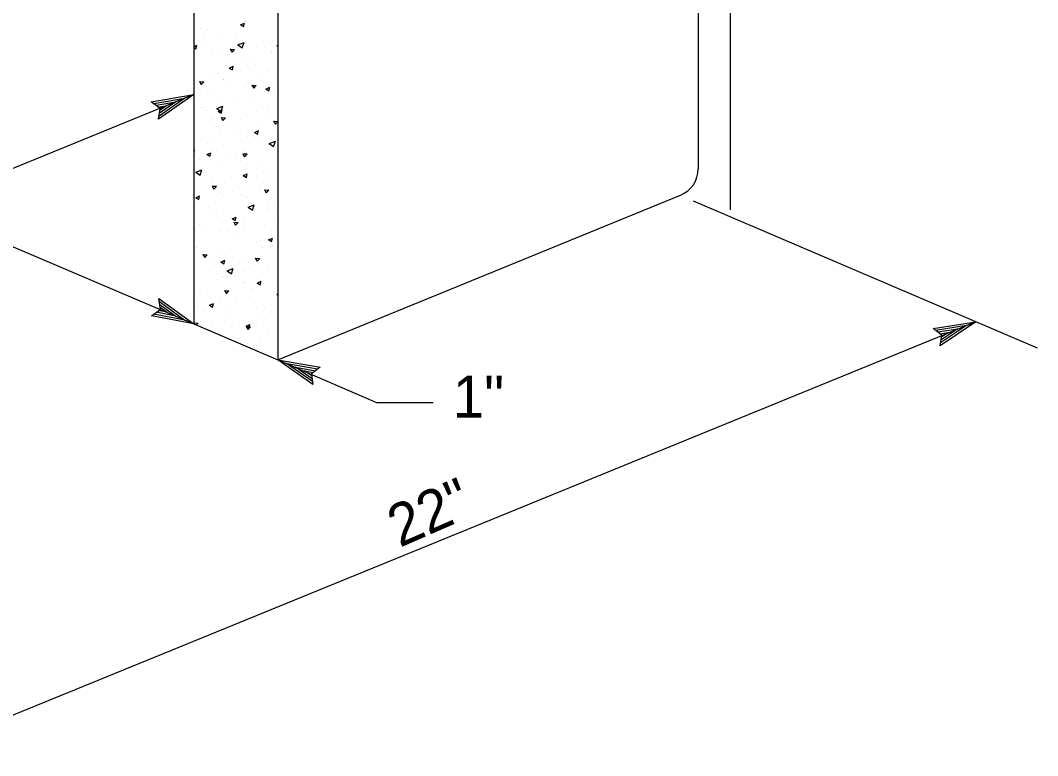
# Model space of a CAD drawing. Extents: x -121875 to -117742, y -103854 to -101122.
# Drawn here: x -120806.9 to -120661.7, y -101531 to -101426.1 of the extents above; entities that cross this region are included whole.
import ezdxf

# ---------------------------------------------------------------- set-up
doc = ezdxf.new("R2010")
doc.units = 0
for name, color, linetype in [('G-MARK', 7, 'Continuous'), ('G-TEXT', 7, 'Continuous'), ('Misc CnstDet(22)', 7, 'Continuous')]:
    doc.layers.add(name, color=color, linetype=linetype)

msp = doc.modelspace()

# ---------------------------------------------------------------- linework, layer by layer
at = {"layer": 'G-MARK'}
for p, q in [((-120862.25, -101435.17), (-120782.14, -101469.41)), ((-120661.71, -101472.87), (-120710.84, -101451.87)), ((-120670.55, -101469.09), (-120822.06, -101531.02))]:
    msp.add_line(p, q, dxfattribs=at)
for points in [[(-120782.14, -101436.65), (-120828.95, -101455.78), (-120827.26, -101459.9), (-120836.23, -101453.95), (-120834.55, -101458.07), (-120895.64, -101483.05)], [(-120770.16, -101474.53), (-120756.08, -101480.63), (-120747.97, -101480.63)]]:
    msp.add_lwpolyline(points, dxfattribs=at)
at = {"layer": 'G-TEXT'}
for p, q in [((-120788.19, -101437.72), (-120782.14, -101436.65)), ((-120787.85, -101437.97), (-120783.41, -101437.18)), ((-120782.14, -101436.65), (-120787.16, -101440.18)), ((-120783.42, -101437.19), (-120787.08, -101439.76)), ((-120782.14, -101436.65), (-120782.14, -101436.65)), ((-120786.94, -101438.65), (-120788.19, -101437.72)), ((-120788.19, -101437.72), (-120788.19, -101437.72)), ((-120787.5, -101438.21), (-120784.69, -101437.71)), ((-120787.2, -101438.46), (-120785.96, -101438.24)), ((-120787.16, -101440.18), (-120786.94, -101438.65)), ((-120784.69, -101437.71), (-120787.05, -101439.37)), ((-120785.96, -101438.24), (-120786.97, -101438.95)), ((-120787.16, -101440.18), (-120787.16, -101440.18)), ((-120786.9, -101467.33), (-120787.1, -101465.78)), ((-120787.1, -101465.78), (-120787.1, -101465.78)), ((-120787.1, -101465.78), (-120782.14, -101469.41)), ((-120787.04, -101466.2), (-120783.4, -101468.86)), ((-120788.17, -101468.23), (-120786.9, -101467.33)), ((-120785.93, -101467.75), (-120787.15, -101467.51)), ((-120786.97, -101466.62), (-120784.67, -101468.3)), ((-120786.95, -101467.01), (-120785.93, -101467.75)), ((-120782.14, -101469.41), (-120788.17, -101468.23)), ((-120788.17, -101468.23), (-120788.17, -101468.23)), ((-120783.41, -101468.86), (-120787.81, -101468)), ((-120784.67, -101468.3), (-120787.51, -101467.75)), ((-120676.63, -101470.06), (-120670.55, -101469.09)), ((-120670.55, -101469.09), (-120675.64, -101472.54)), ((-120670.55, -101469.09), (-120670.55, -101469.09)), ((-120782.14, -101469.41), (-120782.14, -101469.41)), ((-120675.39, -101471.01), (-120676.63, -101470.06)), ((-120676.63, -101470.06), (-120676.63, -101470.06)), ((-120676.29, -101470.31), (-120671.84, -101469.6)), ((-120675.94, -101470.56), (-120673.12, -101470.11)), ((-120675.65, -101470.81), (-120674.41, -101470.62)), ((-120671.85, -101469.61), (-120675.56, -101472.12)), ((-120673.12, -101470.11), (-120675.52, -101471.73)), ((-120674.41, -101470.62), (-120675.43, -101471.31)), ((-120675.64, -101472.54), (-120675.39, -101471.01)), ((-120675.64, -101472.54), (-120675.64, -101472.54)), ((-120765.12, -101478.05), (-120770.16, -101474.53)), ((-120770.16, -101474.53), (-120770.16, -101474.53)), ((-120770.16, -101474.53), (-120764.1, -101475.58)), ((-120765.18, -101477.64), (-120768.88, -101475.06)), ((-120768.87, -101475.06), (-120764.46, -101475.83)), ((-120765.26, -101477.22), (-120767.6, -101475.58)), ((-120767.6, -101475.58), (-120764.75, -101476.08)), ((-120765.29, -101476.83), (-120766.32, -101476.11)), ((-120766.32, -101476.11), (-120765.1, -101476.32)), ((-120764.1, -101475.58), (-120765.35, -101476.51)), ((-120764.1, -101475.58), (-120764.1, -101475.58)), ((-120765.35, -101476.51), (-120765.12, -101478.05)), ((-120765.12, -101478.05), (-120765.12, -101478.05))]:
    msp.add_line(p, q, dxfattribs=at)
at = {"layer": 'Misc CnstDet(22)'}
for p, q in [((-120705.59, -101368.37), (-120705.59, -101453.12)), ((-120710.15, -101383.08), (-120710.15, -101447.27)), ((-120782.14, -101402.21), (-120782.14, -101469.41)), ((-120770.16, -101407.6), (-120770.16, -101474.53)), ((-120775.46, -101426.73), (-120774.89, -101426.47)), ((-120775.46, -101426.73), (-120775.02, -101426.98)), ((-120775.02, -101426.98), (-120774.89, -101426.47)), ((-120774.91, -101426.95), (-120774.91, -101426.95)), ((-120774.85, -101426.21), (-120774.85, -101426.21)), ((-120774.81, -101426.15), (-120774.81, -101426.15)), ((-120782.13, -101428.07), (-120782.13, -101428.07)), ((-120781.22, -101427.25), (-120781.22, -101427.25)), ((-120780.56, -101428.04), (-120780.56, -101428.04)), ((-120780.24, -101427.41), (-120780.24, -101427.41)), ((-120778.18, -101428.2), (-120778.18, -101428.2)), ((-120770.81, -101427.51), (-120770.81, -101427.51)), ((-120782.14, -101429.84), (-120781.69, -101429.64)), ((-120782.14, -101429.97), (-120781.82, -101430.15)), ((-120781.82, -101430.15), (-120781.69, -101429.64)), ((-120781.5, -101429.88), (-120781.5, -101429.88)), ((-120781.01, -101429.83), (-120781.01, -101429.83)), ((-120776.11, -101428.69), (-120776.11, -101428.69)), ((-120775.83, -101429.59), (-120774.96, -101429.25)), ((-120775.83, -101429.59), (-120775.21, -101430.01)), ((-120775.8, -101429.33), (-120775.8, -101429.33)), ((-120775.21, -101430.01), (-120774.96, -101429.26)), ((-120773.12, -101429.8), (-120773.12, -101429.8)), ((-120770.95, -101429), (-120770.95, -101429)), ((-120770.26, -101429.73), (-120770.16, -101429.68)), ((-120770.26, -101429.73), (-120770.16, -101429.79)), ((-120781.56, -101430.26), (-120781.56, -101430.26)), ((-120779.52, -101430.54), (-120779.52, -101430.54)), ((-120778.18, -101430.12), (-120778.18, -101430.12)), ((-120777.37, -101431.16), (-120777.37, -101431.16)), ((-120776.93, -101430.2), (-120776.67, -101430.63)), ((-120776.93, -101430.2), (-120776.3, -101430.25)), ((-120776.67, -101430.64), (-120776.3, -101430.25)), ((-120772.07, -101429.98), (-120772.07, -101429.98)), ((-120771.11, -101430.43), (-120771.11, -101430.43)), ((-120771.04, -101430.63), (-120771.04, -101430.63)), ((-120777.06, -101431.88), (-120777.06, -101431.88)), ((-120777.06, -101432.9), (-120776.49, -101432.64)), ((-120776.63, -101433.15), (-120776.49, -101432.64)), ((-120776.49, -101431.85), (-120776.49, -101431.85)), ((-120774.76, -101431.84), (-120774.76, -101431.84)), ((-120774.49, -101432.48), (-120774.49, -101432.48)), ((-120774.22, -101432.17), (-120774.22, -101432.17)), ((-120773.33, -101432.45), (-120773.33, -101432.45)), ((-120781.47, -101433.26), (-120781.47, -101433.26)), ((-120779.87, -101433.9), (-120779.87, -101433.9)), ((-120778.64, -101433.63), (-120778.64, -101433.63)), ((-120777.06, -101432.9), (-120776.63, -101433.15)), ((-120773.1, -101433.93), (-120773.1, -101433.93)), ((-120771.45, -101433.44), (-120771.45, -101433.44)), ((-120770.27, -101434.22), (-120770.27, -101434.22)), ((-120781.32, -101434.82), (-120781.06, -101435.25)), ((-120781.32, -101434.82), (-120780.69, -101434.87)), ((-120781.06, -101435.25), (-120780.69, -101434.87)), ((-120777.87, -101434.53), (-120777.87, -101434.53)), ((-120777.86, -101434.54), (-120777.86, -101434.54)), ((-120777.52, -101435.31), (-120777.52, -101435.31)), ((-120774.83, -101435.49), (-120774.83, -101435.49)), ((-120774.6, -101434.92), (-120774.6, -101434.92)), ((-120773.84, -101435.35), (-120773.58, -101435.78)), ((-120773.84, -101435.35), (-120773.21, -101435.39)), ((-120773.58, -101435.78), (-120773.21, -101435.39)), ((-120771.86, -101435.9), (-120771.3, -101435.64)), ((-120771.43, -101436.15), (-120771.3, -101435.64)), ((-120781.24, -101436.59), (-120781.24, -101436.59)), ((-120779.9, -101436.1), (-120779.9, -101436.1)), ((-120773.11, -101435.82), (-120773.11, -101435.82)), ((-120771.86, -101435.9), (-120771.43, -101436.15)), ((-120770.41, -101436.19), (-120770.41, -101436.19)), ((-120781.17, -101438.57), (-120781.17, -101438.57)), ((-120780.79, -101438.48), (-120780.79, -101438.48)), ((-120778.84, -101438.67), (-120777.97, -101438.33)), ((-120778.84, -101438.67), (-120778.22, -101439.08)), ((-120778.22, -101439.09), (-120777.97, -101438.33)), ((-120778.2, -101437.55), (-120778.2, -101437.55)), ((-120775.86, -101437.4), (-120775.86, -101437.4)), ((-120773.56, -101437.36), (-120773.56, -101437.36)), ((-120771.68, -101438.66), (-120771.68, -101438.66)), ((-120781.58, -101439.6), (-120781.58, -101439.6)), ((-120780.28, -101438.89), (-120780.28, -101438.89)), ((-120778.66, -101439.07), (-120778.09, -101438.81)), ((-120778.66, -101439.07), (-120778.23, -101439.32)), ((-120778.23, -101439.32), (-120778.09, -101438.81)), ((-120778.23, -101439.97), (-120777.97, -101440.4)), ((-120778.23, -101439.97), (-120777.6, -101440.01)), ((-120777.97, -101440.4), (-120777.6, -101440.01)), ((-120777.13, -101439.87), (-120777.13, -101439.87)), ((-120773.14, -101439.14), (-120773.14, -101439.14)), ((-120771.13, -101439.78), (-120771.13, -101439.78)), ((-120779.67, -101440.24), (-120779.67, -101440.24)), ((-120779.24, -101441.39), (-120779.24, -101441.39)), ((-120776.83, -101440.54), (-120776.83, -101440.54)), ((-120776.52, -101441.19), (-120776.52, -101441.19)), ((-120775.52, -101440.18), (-120775.52, -101440.18)), ((-120772.94, -101441.13), (-120772.94, -101441.13)), ((-120770.77, -101441.48), (-120770.77, -101441.48)), ((-120770.75, -101440.49), (-120770.49, -101440.92)), ((-120770.75, -101440.49), (-120770.16, -101440.53)), ((-120770.49, -101440.92), (-120770.16, -101440.57)), ((-120778.39, -101442.34), (-120778.39, -101442.34)), ((-120775.71, -101442.29), (-120775.71, -101442.29)), ((-120774.51, -101441.83), (-120774.51, -101441.83)), ((-120774.49, -101442.69), (-120774.49, -101442.69)), ((-120773.46, -101442.07), (-120772.9, -101441.81)), ((-120773.46, -101442.07), (-120773.03, -101442.32)), ((-120773.03, -101442.32), (-120772.9, -101441.81)), ((-120772.88, -101442.59), (-120772.88, -101442.59)), ((-120771.47, -101442.78), (-120771.47, -101442.78)), ((-120780.13, -101443.67), (-120780.13, -101443.67)), ((-120779.89, -101443.25), (-120779.89, -101443.25)), ((-120777.89, -101443.88), (-120777.89, -101443.88)), ((-120774.2, -101443.6), (-120774.2, -101443.6)), ((-120771.76, -101444.34), (-120771.76, -101444.34)), ((-120771.37, -101443.67), (-120770.49, -101443.34)), ((-120771.37, -101443.67), (-120770.74, -101444.09)), ((-120770.74, -101444.09), (-120770.49, -101443.34)), ((-120782.14, -101444.62), (-120782, -101444.63)), ((-120782.14, -101444.78), (-120782, -101444.63)), ((-120781.26, -101445.93), (-120781.26, -101445.93)), ((-120780.26, -101445.24), (-120779.69, -101444.98)), ((-120780.26, -101445.24), (-120779.83, -101445.49)), ((-120779.83, -101445.49), (-120779.69, -101444.98)), ((-120779.66, -101444.81), (-120779.66, -101444.81)), ((-120777.59, -101445.38), (-120777.59, -101445.38)), ((-120776.17, -101445.72), (-120776.17, -101445.72)), ((-120775.14, -101445.11), (-120774.88, -101445.54)), ((-120775.14, -101445.11), (-120774.51, -101445.15)), ((-120774.88, -101445.54), (-120774.51, -101445.16)), ((-120774.85, -101444.84), (-120774.85, -101444.84)), ((-120780.92, -101447.28), (-120780.92, -101447.28)), ((-120778.23, -101446.89), (-120778.23, -101446.89)), ((-120775.47, -101446.07), (-120775.47, -101446.07)), ((-120772.83, -101446.68), (-120772.83, -101446.68)), ((-120771.34, -101447.35), (-120771.34, -101447.35)), ((-120781.86, -101447.74), (-120780.98, -101447.4)), ((-120781.86, -101447.74), (-120781.23, -101448.16)), ((-120781.23, -101448.16), (-120780.98, -101447.4)), ((-120776.73, -101448.54), (-120776.73, -101448.54)), ((-120775.07, -101448.24), (-120774.5, -101447.98)), ((-120775.07, -101448.24), (-120774.63, -101448.49)), ((-120774.63, -101448.49), (-120774.5, -101447.98)), ((-120773.16, -101448.49), (-120773.16, -101448.49)), ((-120772.22, -101447.77), (-120772.22, -101447.77)), ((-120781.6, -101448.94), (-120781.6, -101448.94)), ((-120780, -101449.74), (-120780, -101449.74)), ((-120779.53, -101449.73), (-120779.27, -101450.16)), ((-120779.53, -101449.73), (-120778.91, -101449.77)), ((-120779.45, -101448.9), (-120779.45, -101448.9)), ((-120779.27, -101450.16), (-120778.91, -101449.78)), ((-120772.61, -101449.82), (-120772.61, -101449.82)), ((-120772.05, -101450.25), (-120771.79, -101450.68)), ((-120772.05, -101450.25), (-120771.42, -101450.3)), ((-120771.16, -101449.12), (-120771.16, -101449.12)), ((-120781.86, -101451.41), (-120781.3, -101451.15)), ((-120781.86, -101451.41), (-120781.43, -101451.66)), ((-120781.43, -101451.66), (-120781.3, -101451.15)), ((-120778.33, -101450.65), (-120778.33, -101450.65)), ((-120778, -101451.02), (-120778, -101451.02)), ((-120776.54, -101450.54), (-120776.54, -101450.54)), ((-120775.49, -101450.95), (-120775.49, -101450.95)), ((-120775.25, -101451.04), (-120775.25, -101451.04)), ((-120774.53, -101451.17), (-120774.53, -101451.17)), ((-120771.79, -101450.68), (-120771.42, -101450.3)), ((-120770.16, -101474.53), (-120712.68, -101451.04)), ((-120779.92, -101452.59), (-120779.92, -101452.59)), ((-120778.97, -101452.24), (-120778.97, -101452.24)), ((-120774.38, -101452.75), (-120773.5, -101452.41)), ((-120774.38, -101452.75), (-120773.76, -101453.17)), ((-120774.37, -101452.7), (-120774.37, -101452.7)), ((-120773.87, -101452.29), (-120773.87, -101452.29)), ((-120773.75, -101453.17), (-120773.5, -101452.41)), ((-120771.54, -101453), (-120771.54, -101453)), ((-120771.5, -101452.13), (-120771.5, -101452.13)), ((-120770.49, -101452.33), (-120770.49, -101452.33)), ((-120779.26, -101453.49), (-120779.26, -101453.49)), ((-120778.79, -101454.09), (-120778.79, -101454.09)), ((-120777.91, -101453.22), (-120777.91, -101453.22)), ((-120776.67, -101454.41), (-120776.1, -101454.15)), ((-120776.67, -101454.41), (-120776.23, -101454.66)), ((-120776.23, -101454.66), (-120776.1, -101454.15)), ((-120774.87, -101454.18), (-120774.87, -101454.18)), ((-120774.21, -101453.54), (-120774.21, -101453.54)), ((-120782.07, -101454.93), (-120782.07, -101454.93)), ((-120781.28, -101455.28), (-120781.28, -101455.28)), ((-120780.53, -101455.96), (-120780.53, -101455.96)), ((-120776.44, -101454.87), (-120776.18, -101455.3)), ((-120776.44, -101454.87), (-120775.82, -101454.92)), ((-120776.18, -101455.3), (-120775.82, -101454.92)), ((-120775.14, -101454.76), (-120775.14, -101454.76)), ((-120771.1, -101456.06), (-120771.1, -101456.06)), ((-120770.42, -101454.76), (-120770.42, -101454.76)), ((-120782.06, -101457.26), (-120782.06, -101457.26)), ((-120778.25, -101456.23), (-120778.25, -101456.23)), ((-120777.32, -101456.23), (-120777.32, -101456.23)), ((-120776.4, -101457.23), (-120776.4, -101457.23)), ((-120774.83, -101456.14), (-120774.83, -101456.14)), ((-120772.56, -101457.53), (-120772.56, -101457.53)), ((-120771.47, -101457.41), (-120770.9, -101457.15)), ((-120771.47, -101457.41), (-120771.04, -101457.66)), ((-120771.04, -101457.66), (-120770.9, -101457.15)), ((-120781.79, -101458.43), (-120781.79, -101458.43)), ((-120781.62, -101458.29), (-120781.62, -101458.29)), ((-120773.19, -101457.83), (-120773.19, -101457.83)), ((-120772.36, -101458.53), (-120772.36, -101458.53)), ((-120771.18, -101458.46), (-120771.18, -101458.46)), ((-120770.88, -101458.19), (-120770.88, -101458.19)), ((-120780.94, -101459.02), (-120780.94, -101459.02)), ((-120780.83, -101459.49), (-120780.57, -101459.92)), ((-120780.83, -101459.49), (-120780.21, -101459.54)), ((-120780.57, -101459.92), (-120780.21, -101459.54)), ((-120778.27, -101460.58), (-120777.7, -101460.31)), ((-120778.1, -101459.31), (-120778.1, -101459.31)), ((-120777.83, -101460.83), (-120777.7, -101460.32)), ((-120777.66, -101459.71), (-120777.66, -101459.71)), ((-120776.56, -101459.88), (-120776.56, -101459.88)), ((-120773.35, -101460.02), (-120773.09, -101460.44)), ((-120773.35, -101460.02), (-120772.73, -101460.06)), ((-120773.09, -101460.45), (-120772.72, -101460.06)), ((-120779.73, -101460.59), (-120779.73, -101460.59)), ((-120778.27, -101460.58), (-120777.83, -101460.83)), ((-120777.39, -101461.82), (-120776.52, -101461.48)), ((-120777.39, -101461.82), (-120776.77, -101462.24)), ((-120776.98, -101461.07), (-120776.98, -101461.07)), ((-120776.77, -101462.24), (-120776.52, -101461.49)), ((-120774.97, -101461.89), (-120774.97, -101461.89)), ((-120774.55, -101460.51), (-120774.55, -101460.51)), ((-120774.15, -101461.36), (-120774.15, -101461.36)), ((-120773.62, -101461), (-120773.62, -101461)), ((-120771.52, -101461.47), (-120771.52, -101461.47)), ((-120781.4, -101462.45), (-120781.4, -101462.45)), ((-120779.94, -101461.93), (-120779.94, -101461.93)), ((-120778.93, -101462.18), (-120778.93, -101462.18)), ((-120778.69, -101463.09), (-120778.69, -101463.09)), ((-120777.93, -101462.57), (-120777.93, -101462.57)), ((-120773.07, -101463.58), (-120772.5, -101463.31)), ((-120773.03, -101463.12), (-120773.03, -101463.12)), ((-120772.64, -101463.83), (-120772.5, -101463.32)), ((-120770.22, -101463.19), (-120770.22, -101463.19)), ((-120781.31, -101464.62), (-120781.31, -101464.62)), ((-120780.19, -101464.65), (-120780.19, -101464.65)), ((-120777.74, -101464.64), (-120777.48, -101465.06)), ((-120777.74, -101464.64), (-120777.12, -101464.68)), ((-120777.48, -101465.07), (-120777.12, -101464.68)), ((-120777.44, -101464.5), (-120777.44, -101464.5)), ((-120774.89, -101463.47), (-120774.89, -101463.47)), ((-120774.89, -101463.52), (-120774.89, -101463.52)), ((-120773.94, -101464.39), (-120773.94, -101464.39)), ((-120773.07, -101463.58), (-120772.64, -101463.83)), ((-120770.7, -101464.74), (-120770.7, -101464.74)), ((-120770.2, -101463.41), (-120770.2, -101463.41)), ((-120781.8, -101465.78), (-120781.8, -101465.78)), ((-120778.27, -101465.58), (-120778.27, -101465.58)), ((-120776.15, -101465.94), (-120776.15, -101465.94)), ((-120770.26, -101465.16), (-120770.16, -101465.33)), ((-120770.26, -101465.16), (-120770.16, -101465.17)), ((-120781.65, -101467.63), (-120781.65, -101467.63)), ((-120781.46, -101467.12), (-120781.46, -101467.12)), ((-120780.71, -101467.67), (-120780.71, -101467.67)), ((-120779.87, -101466.75), (-120779.3, -101466.48)), ((-120779.87, -101466.75), (-120779.44, -101467)), ((-120779.44, -101467), (-120779.3, -101466.49)), ((-120777.04, -101467.08), (-120777.04, -101467.08)), ((-120773.49, -101466.55), (-120773.49, -101466.55)), ((-120773.21, -101467.17), (-120773.21, -101467.17)), ((-120771.97, -101467.21), (-120771.97, -101467.21)), ((-120777.42, -101468.42), (-120777.42, -101468.42)), ((-120772.28, -101468.38), (-120772.28, -101468.38)), ((-120771.2, -101467.8), (-120771.2, -101467.8)), ((-120782.14, -101469.41), (-120770.16, -101474.53)), ((-120782.13, -101469.26), (-120782.01, -101469.47)), ((-120782.13, -101469.26), (-120781.51, -101469.3)), ((-120781.76, -101469.57), (-120781.51, -101469.3)), ((-120779.6, -101469.43), (-120779.6, -101469.43)), ((-120776.76, -101469.72), (-120776.76, -101469.72)), ((-120776.58, -101469.22), (-120776.58, -101469.22)), ((-120774.67, -101469.75), (-120774.11, -101469.48)), ((-120774.67, -101469.75), (-120774.24, -101470)), ((-120774.65, -101469.78), (-120774.39, -101470.21)), ((-120774.65, -101469.78), (-120774.03, -101469.82)), ((-120774.58, -101469.86), (-120774.58, -101469.86)), ((-120774.39, -101470.21), (-120774.03, -101469.82)), ((-120774.24, -101470), (-120774.11, -101469.49)), ((-120773.23, -101469.68), (-120773.23, -101469.68)), ((-120778.68, -101470.89), (-120778.68, -101470.89)), ((-120775.64, -101471.48), (-120775.64, -101471.48)), ((-120772.81, -101471.77), (-120772.81, -101471.77)), ((-120771.54, -101470.81), (-120771.54, -101470.81)), ((-120774.49, -101472.15), (-120774.49, -101472.15)), ((-120770.37, -101473.43), (-120770.37, -101473.43)), ((-120771.69, -101473.53), (-120771.69, -101473.53))]:
    msp.add_line(p, q, dxfattribs=at)
msp.add_arc((-120714.22, -101447.27), 4.07, 292.2327, 0, dxfattribs=at)

# ---------------------------------------------------------------- texts
msp.add_text('1"', height=6, dxfattribs=at).set_placement((-120745.16, -101482.78))
msp.add_text('22"', height=6, rotation=23.6156, dxfattribs=at).set_placement((-120752.75, -101501.37))

doc.saveas('drawing.dxf')
